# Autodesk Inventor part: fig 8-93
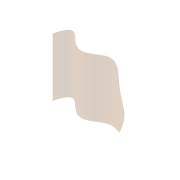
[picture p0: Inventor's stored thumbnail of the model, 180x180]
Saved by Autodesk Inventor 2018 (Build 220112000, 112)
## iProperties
Shininess: 64.0
Length Units: 11269
Angle Units: 11279
Time Units: 11290
Mass Units: 11283
Length Display Precision: 3
Angle Display Precision: 2
Compacted: True
Part Number: fig 8-93
Document SubType Name: Modeling
Created: 2003-08
Designer: Owner
Manufacturer: Standard
Standards Organization: Custom
Density: 1 g/cm^3
Material: Generic
Appearance: Default
Density: 0.0
Volumn: 0.0
Area: 0.0
PropertySet Name: Model Information
Control State: 0
Master: False
Checked Out: False
Author: Owner
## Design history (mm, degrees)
sketch "Sketch1"
  geometry: 7 further points
  constraints: 7 other
  dimensions: "d0" = 80 horizontal distance of point (40, 1.742) point (-40, -4.065); "d1" = 40 horizontal distance of point (0, 0) point (-40, -4.065)
extrude_surface "ExtrusionSrf1" sketch "Sketch1" dims "d2" = 80, "d3" = 0
sketch "Sketch2"
  geometry: L1 (40, 0)-(40, -40) reference; L2 (-40, 0)-(-40, -40) reference; 7 further points
  constraints: 2 point on line, 7 other
extrude_surface "ExtrusionSrf2" sketch "Sketch2" dims "d4" = 80, "d5" = 0
workplane "Work Plane1"
sketch "Sketch4"
  geometry: L1 (70.027, 16.004)-(-4, 16.004); A1 r 29.004 centre (-4, -13) between (-4, 16.004) and (-2.981, -41.986)
  constraints: 2 end point, 2 point on circle, 1 centre point, 1 horizontal, 1 tangent
feature "Trim1" sketch "Sketch4"
body "Srf1"
body "Srf2"
other parameters: "d6" = -54.75
